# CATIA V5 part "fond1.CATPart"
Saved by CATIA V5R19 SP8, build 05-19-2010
Part number: Part1.1.2
Bounding box of the stored display mesh (mm): x 0 to 85, y 0 to 1550, z 0 to 572
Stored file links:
  G:\EU_thinkMotion\CFAO_2010\SIL_groupe2\SIL_groupe2\A reprendre\fnongaibaa\fnongaibaa\fond1.CATPart
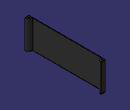
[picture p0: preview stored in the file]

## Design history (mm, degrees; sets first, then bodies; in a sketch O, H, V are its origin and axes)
Body1 (main body)
  Sketch1 on yz-plane, origin (0, 0, 0), H (0, 1, 0), V (0, 0, 1)
    line L1 (0, 0) -> (1550, 0)
    line L2 (1550, 0) -> (1550, 572)
    line L3 (1550, 572) -> (0, 572)
    line L4 (0, 572) -> (0, 0)
    length L1 = 1550
    length L2 = 572
    horizontal: L1 H, L3 H
    vertical: L2 V, L4 V
  Pad1: profile Sketch1, direction (1, 0, 0), length 5
  Sketch2 on end face of Pad1, origin (5, 0, 0), H (0, 1, 0), V (0, 0, 1)
    line L1 (1550, 572) -> (1470, 572)
    line L2 (1470, 572) -> (1470, 0)
    line L3 (1470, 0) -> (1550, 0)
    line L4 (1550, 0) -> (1550, 572)
    reference projected line E1 (1550, 0) -> (1550, 80) from edge [face of Pad1 from Sketch1.L2 | end face of Pad1]
    reference projected line E2 (150, 572) -> (0, 572) from edge [face of Pad1 from Sketch1.L3 | end face of Pad1]
    reference projected line E3 (0, 0) -> (150, 0) from edge [face of Pad1 from Sketch1.L1 | end face of Pad1]
    length L1 = 80
    horizontal: L1 H, L3 H
    vertical: L2 V, L4 V
    coincidence: L4 E1, L1 E2, L3 E3
  Shaft1: profile Sketch2, axis Sketch2.L4, angle 90
  Sketch3 on end face of Pad1, origin (5, 0, 0), H (0, 1, 0), V (0, 0, 1)
    line L1 (0, 572) -> (80, 572)
    line L2 (80, 572) -> (80, 0)
    line L3 (80, 0) -> (0, 0)
    line L4 (0, 0) -> (0, 572)
    reference projected line E1 (0, 80) -> (0, 0) from edge [face of Pad1 from Sketch1.L4 | end face of Pad1]
    reference projected line E2 (150, 572) -> (0, 572) from edge [face of Shaft1 | end face of Pad1]
    reference projected line E3 (0, 0) -> (150, 0) from edge [face of Shaft1 | end face of Pad1]
    length L1 = 80
    horizontal: L1 H, L3 H
    vertical: L2 V, L4 V
    coincidence: L4 E1, L1 E2, L3 E3
  Shaft2: profile Sketch3, axis Sketch3.L4, angle 90
  Sketch4 on face of Shaft2, origin (32.0495, 37.8886, 572), H (1, 0, 0), V (0, 1, 0)
    point P1 (2.9505, -2.8886)
    reference projected line E1 (-32.0495, -37.8886) -> (-27.0495, -37.8886) from edge [face of Shaft2 | face of Shaft2]
    reference projected line E2 (-32.0495, 1177.1114) -> (-32.0495, -37.8886) from edge [start face of Pad1 | face of Shaft2]
    distance P1 E1 = 35
    distance P1 E2 = 35
  Hole1: placed by Sketch4, at (35, 35, 572) direction (0, 0, -1), diameter 20, up to face of Shaft2
  Sketch5 on face of Shaft2, origin (53.047, 1186.4348, 572), H (1, 0, 0), V (0, 1, 0)
    point P1 (-18.047, 328.5652)
    reference projected line E1 (-53.047, 363.5652) -> (-48.047, 363.5652) from edge [face of Shaft2 | face of Shaft1]
    reference projected line E2 (-53.047, 28.5652) -> (-53.047, -1186.4348) from edge [start face of Pad1 | face of Shaft2]
    distance P1 E1 = 35
    distance P1 E2 = 35
  Hole2: placed by Sketch5, at (35, 1515, 572) direction (0, 0, -1), diameter 20, up to face of Shaft2
  Sketch6 on face of Shaft1, origin (38.4847, 1550, 258.9796), H (1, 0, 0), V (0, 0, -1)
    point P1 (4.0153, 243.9796)
    axis line L1 (4.0153, -380) -> (4.0153, -60)
    reference projected line E1 (-38.4847, 258.9796) -> (-38.4847, -313.0204) from edge [start face of Pad1 | face of Shaft1]
    reference projected line E2 (46.5153, -313.0204) -> (46.5153, 258.9796) from edge [face of Shaft1 from Sketch2.L2 | face of Shaft1]
    reference projected line E3 (-38.4847, 258.9796) -> (-33.4847, 258.9796) from edge [face of Shaft1 | face of Shaft2]
    distance P1 E3 = 15
    vertical: L1 V
    symmetry: E1 E2 L1
    coincidence: P1 L1
  Hole3: placed by Sketch6, at (42.5, 1550, 15) direction (0, -1, 0), diameter 5, through (limit type 3)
